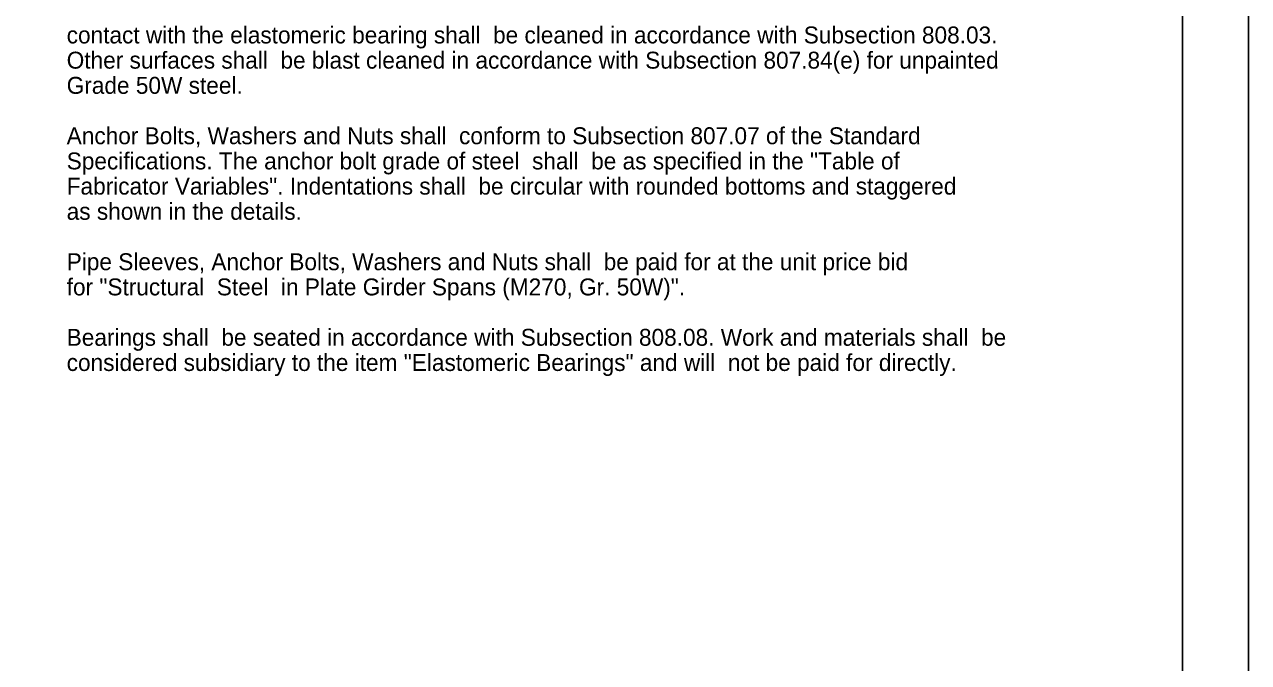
# Model space of a CAD drawing. Extents: x -193 to 149, y 507 to 725.
# Drawn here: x 58.2 to 148.7, y 554.2 to 601.4 of the extents above; entities that cross this region are included whole.
import ezdxf

# ---------------------------------------------------------------- set-up
doc = ezdxf.new("R2010")
doc.units = 0
for name, color, linetype in [('border', 7, 'Continuous'), ('Border 2660-Hwy18 - Level 62', 7, 'Continuous'), ('Level 40', 7, 'Continuous')]:
    doc.layers.add(name, color=color, linetype=linetype)

msp = doc.modelspace()

# ---------------------------------------------------------------- linework, layer by layer
at = {"layer": 'border'}
msp.add_line((143.779, 513.86), (143.779, 719.311), dxfattribs=at)
at = {"layer": 'Border 2660-Hwy18 - Level 62'}
msp.add_lwpolyline([(-192.533, 725.169), (148.651, 725.169), (148.651, 507.073), (-192.533, 507.073)], close=True, dxfattribs=at)

# ---------------------------------------------------------------- texts
at = {"layer": 'Level 40'}
for s, p in [('contact with the elastomeric bearing shall  be cleaned in accordance with Subsection 808.03.', (61.341, 599.956)), ('Other surfaces shall  be blast cleaned in accordance with Subsection 807.84(e) for unpainted', (61.341, 598.094)), ('Grade 50W steel.', (61.341, 596.233)), ('Anchor Bolts, Washers and Nuts shall  conform to Subsection 807.07 of the Standard', (61.341, 592.51)), ('Specifications. The anchor bolt grade of steel  shall  be as specified in the "Table of', (61.341, 590.648)), ('Fabricator Variables". Indentations shall  be circular with rounded bottoms and staggered', (61.341, 588.787)), ('as shown in the details.', (61.341, 586.925)), ('Pipe Sleeves, Anchor Bolts, Washers and Nuts shall  be paid for at the unit price bid', (61.341, 583.202)), ('for "Structural  Steel  in Plate Girder Spans (M270, Gr. 50W)".', (61.341, 581.34)), ('Bearings shall  be seated in accordance with Subsection 808.08. Work and materials shall  be', (61.341, 577.617)), ('considered subsidiary to the item "Elastomeric Bearings" and will  not be paid for directly.', (61.341, 575.756))]:
    msp.add_text(s, height=1.25, dxfattribs=at).set_placement(p)

doc.saveas('drawing.dxf')
